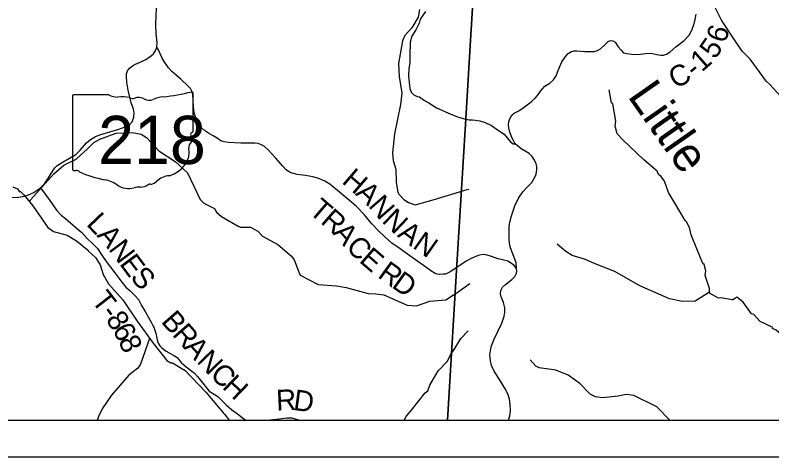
# Model space of a CAD drawing. Extents: x -1.8 to 75.7, y -2 to 25.
# Drawn here: x 46.582 to 48.65, y 15.612 to 16.82 of the extents above; entities that cross this region are included whole.
import ezdxf

# ---------------------------------------------------------------- set-up
doc = ezdxf.new("R2010")
doc.units = 0
for name, color, linetype in [('GM_X_County_Road', 7, 'Continuous'), ('GM_X_County_Road_Text', 7, 'Continuous'), ('GM_X_Minor_River', 7, 'Continuous'), ('GM_X_Minor_River_Text', 7, 'Continuous'), ('GM_X_State_Location', 7, 'Continuous'), ('GM_X_State_Route', 7, 'Continuous'), ('GM_X_State_Shield', 7, 'Continuous'), ('GM_X_Township', 7, 'Continuous'), ('GM_X_Township_Road', 7, 'Continuous'), ('GM_X_Township_Road_Text', 7, 'Continuous'), ('SH_Data', 7, 'Continuous')]:
    doc.layers.add(name, color=color, linetype=linetype)

msp = doc.modelspace()

# ---------------------------------------------------------------- linework, layer by layer
at = {"layer": 'GM_X_County_Road'}
for points in [[(47.7035, 16.83), (47.6954, 16.8181), (47.6889, 16.8088), (47.6859, 16.7983), (47.677, 16.7799), (47.6663, 16.7623), (47.6614, 16.7463), (47.6604, 16.7082), (47.6605, 16.6896), (47.6576, 16.6736), (47.6574, 16.6531), (47.6608, 16.6193), (47.6644, 16.6089), (47.6713, 16.6015), (47.6806, 16.5977), (47.6874, 16.5962), (47.7007, 16.5867), (47.7128, 16.5796), (47.7337, 16.5667), (47.7641, 16.5525), (47.788, 16.543), (47.8062, 16.5371), (47.8137, 16.5356), (47.8231, 16.5337), (47.8315, 16.5334)], [(47.9438, 16.4769), (47.9401, 16.4838), (47.9344, 16.5001), (47.9308, 16.5116), (47.93, 16.5197), (47.931, 16.5288), (47.9345, 16.5385), (47.9393, 16.5465), (47.946, 16.5517), (47.9582, 16.5584), (47.9708, 16.5667), (47.9923, 16.5826), (48.0028, 16.5927), (48.0091, 16.6), (48.0179, 16.6118), (48.0296, 16.6254), (48.0432, 16.6341), (48.053, 16.6428), (48.0597, 16.6522), (48.068, 16.6727), (48.0761, 16.6922), (48.0867, 16.7075), (48.0934, 16.7147), (48.1021, 16.72), (48.1092, 16.7224), (48.1171, 16.7226), (48.1392, 16.7208), (48.1554, 16.72), (48.1652, 16.7206), (48.1733, 16.723), (48.1819, 16.7279), (48.1935, 16.7383), (48.2027, 16.7473), (48.2088, 16.7502), (48.2157, 16.7496), (48.2214, 16.7457), (48.2301, 16.7329), (48.2378, 16.7242), (48.2447, 16.7171), (48.2531, 16.7149), (48.2669, 16.7129), (48.2827, 16.7126), (48.3048, 16.7149), (48.3204, 16.7155), (48.3356, 16.7122), (48.3462, 16.7104), (48.3543, 16.7106), (48.3624, 16.7133), (48.3718, 16.7198), (48.388, 16.7331), (48.4103, 16.7504), (48.4241, 16.7652), (48.4312, 16.7788), (48.4367, 16.7942), (48.4407, 16.8078), (48.443, 16.8224)], [(47.7998, 16.1373), (47.792, 16.1321), (47.7888, 16.1299), (47.7713, 16.1181), (47.7583, 16.112), (47.7514, 16.1112), (47.7429, 16.1104), (47.7352, 16.1118), (47.7295, 16.1138), (47.7177, 16.1203), (47.7048, 16.1303), (47.6609, 16.1615), (47.6339, 16.1806), (47.6118, 16.1968), (47.5923, 16.2141), (47.5751, 16.2305), (47.5572, 16.2488), (47.5355, 16.2751), (47.5142, 16.2975), (47.4968, 16.3125), (47.4681, 16.3354), (47.4422, 16.3575), (47.4284, 16.3663), (47.4123, 16.3732), (47.3959, 16.3776), (47.3756, 16.3815), (47.3527, 16.3837), (47.3387, 16.3874), (47.3318, 16.3902), (47.3229, 16.3967), (47.3135, 16.407), (47.2934, 16.4294), (47.274, 16.4517), (47.2638, 16.4606), (47.2555, 16.4655), (47.2464, 16.4685), (47.237, 16.4702), (47.223, 16.4695), (47.1991, 16.4698), (47.165, 16.4718), (47.1532, 16.4732), (47.1445, 16.4764), (47.1339, 16.4833), (47.123, 16.4902), (47.1102, 16.4971), (47.1, 16.5045), (47.0911, 16.512), (47.083, 16.5227), (47.0773, 16.5349), (47.0718, 16.5525), (47.0694, 16.5704), (47.0683, 16.5864), (47.0679, 16.6025), (47.0653, 16.6115), (47.0611, 16.6189), (47.0552, 16.6255), (47.0347, 16.6445), (47.0104, 16.6661), (47.0014, 16.676), (46.9894, 16.693), (46.9831, 16.7039), (46.9737, 16.7249), (46.9691, 16.7321)], [(47.8315, 16.5334), (47.84, 16.5331), (47.8522, 16.5305), (47.8666, 16.5265), (47.8837, 16.5181), (47.9034, 16.5043), (47.9188, 16.4946), (47.9353, 16.4739), (47.9431, 16.468), (47.9486, 16.4681)], [(47.9525, 16.1268), (47.9513, 16.1426), (47.9422, 16.1676), (47.9359, 16.1832), (47.9328, 16.1952), (47.932, 16.209), (47.9318, 16.226), (47.9322, 16.2417), (47.9337, 16.2536), (47.9385, 16.2715), (47.9479, 16.2987), (47.9576, 16.319), (47.9696, 16.3366), (47.9793, 16.348), (47.9937, 16.3626), (48.0014, 16.3746), (48.0059, 16.3853), (48.0079, 16.3965), (48.0073, 16.4058), (48.0057, 16.4129), (48.0014, 16.4237), (47.9947, 16.4334), (47.9866, 16.4411), (47.9759, 16.4478), (47.9653, 16.4547), (47.9486, 16.4681), (47.9438, 16.4769)], [(47.9305, 15.7121), (47.9343, 15.7245), (47.9354, 15.7379), (47.9347, 15.7564), (47.9329, 15.7696), (47.9281, 15.7844), (47.9213, 15.7983), (47.9101, 15.8163), (47.891, 15.846), (47.8839, 15.8622), (47.881, 15.8743), (47.8794, 15.8913), (47.8807, 15.9023), (47.8829, 15.9127), (47.8901, 15.9324), (47.9117, 15.9777), (47.9183, 15.9969), (47.9206, 16.0078), (47.9206, 16.0197), (47.917, 16.034), (47.9104, 16.0498), (47.9088, 16.058), (47.9092, 16.0666), (47.9136, 16.076), (47.9218, 16.0838), (47.9393, 16.0974), (47.948, 16.1054), (47.9521, 16.1145), (47.9532, 16.1211), (47.9525, 16.1268), (47.9458, 16.1353), (47.9389, 16.1406), (47.9286, 16.1467), (47.9174, 16.1499), (47.9018, 16.1538), (47.8785, 16.1621), (47.8683, 16.1646), (47.86, 16.165), (47.847, 16.1623), (47.8302, 16.1556), (47.8145, 16.1471), (47.7998, 16.1373)]]:
    msp.add_lwpolyline(points, dxfattribs=at)
at = {"layer": 'GM_X_Minor_River'}
for points in [[(48.675, 16.5965), (48.6436, 16.6309), (48.6355, 16.638), (48.5908, 16.6994), (48.5684, 16.721), (48.5438, 16.7582), (48.5128, 16.8063), (48.4718, 16.8889), (48.463, 16.8975), (48.437, 16.9504)], [(47.687, 16.835), (47.6834, 16.8146), (47.6658, 16.7852), (47.6471, 16.7645), (47.6402, 16.7499), (47.63, 16.6872), (47.6316, 16.6522), (47.6385, 16.6061), (47.6349, 16.5754), (47.6185, 16.4951), (47.6135, 16.4436), (47.6155, 16.4223), (47.6224, 16.3989), (47.6235, 16.3624), (47.628, 16.3357), (47.6305, 16.3307), (47.644, 16.3158), (47.657, 16.3074), (47.675, 16.3015), (47.7249, 16.3151), (47.8176, 16.3429), (47.8222, 16.3439)], [(48.5428, 16.0417), (48.51, 16.0467), (48.5044, 16.0463), (48.4798, 16.06), (48.4794, 16.0725), (48.4676, 16.1078), (48.4691, 16.1207), (48.4653, 16.1382), (48.4615, 16.1412), (48.4453, 16.1811), (48.4293, 16.2195), (48.4252, 16.2392), (48.4168, 16.2544), (48.4134, 16.2586), (48.3835, 16.3072), (48.3672, 16.3345), (48.3563, 16.366), (48.3475, 16.3789), (48.3404, 16.3842), (48.3362, 16.3933), (48.2995, 16.4252), (48.2439, 16.4782), (48.2272, 16.4953), (48.2219, 16.5162), (48.2238, 16.5299), (48.2154, 16.5774), (48.212, 16.5796), (48.2052, 16.6157)], [(46.6217, 16.3098), (46.6253, 16.3157), (46.6879, 16.3855), (46.7151, 16.4093), (46.7485, 16.4264), (46.78, 16.4547), (46.7971, 16.4712), (46.814, 16.4805), (46.858, 16.497), (46.9019, 16.4986), (46.9267, 16.4948), (46.9412, 16.4856), (46.9748, 16.4484), (47.0197, 16.4197), (47.0528, 16.3886), (47.0873, 16.3161), (47.0972, 16.3067), (47.1046, 16.3023), (47.1266, 16.2913), (47.1323, 16.2813), (47.1463, 16.2691), (47.1913, 16.2428)], [(46.5758, 16.3501), (46.5883, 16.3448), (46.5939, 16.3369), (46.5966, 16.3376), (46.606, 16.3285), (46.6306, 16.2982), (46.6533, 16.2652), (46.6719, 16.2394), (46.681, 16.2326), (46.687, 16.2284), (46.7241, 16.2182), (46.7498, 16.2027), (46.7793, 16.1788), (46.782, 16.1754), (46.8013, 16.1576), (46.8141, 16.1371), (46.8225, 16.1105), (46.8376, 16.0851), (46.8762, 16.0418), (46.9156, 15.9834), (46.9591, 15.9227), (46.9966, 15.876), (47.0075, 15.8692), (47.0125, 15.8696), (47.0469, 15.848), (47.1029, 15.7889), (47.1517, 15.7312), (47.1543, 15.7286), (47.1668, 15.7121)], [(47.1913, 16.2428), (47.1976, 16.2397), (47.2252, 16.2403), (47.2453, 16.2291), (47.2577, 16.2154), (47.3001, 16.1928), (47.3369, 16.1612), (47.3442, 16.1507), (47.3586, 16.1153), (47.3614, 16.1092), (47.4106, 16.0833), (47.4603, 16.0794), (47.4871, 16.0755), (47.547, 16.0588), (47.5682, 16.0578), (47.5892, 16.0552), (47.653, 16.0269), (47.6787, 16.0246), (47.715, 16.0375), (47.7589, 16.0414), (47.7801, 16.0552), (47.7863, 16.0591), (47.8242, 16.0864)], [(48.4794, 16.0623), (48.4403, 16.0378), (48.4055, 16.0367), (48.3702, 16.0443), (48.2889, 16.0799), (48.2205, 16.1189), (48.172, 16.1376), (48.1384, 16.1527), (48.1043, 16.1625), (48.0869, 16.1733), (48.0629, 16.1938)], [(48.8468, 15.7937), (48.8248, 15.8084), (48.7884, 15.8395), (48.7684, 15.8543), (48.7408, 15.888), (48.7377, 15.8884), (48.7059, 15.9294), (48.6799, 15.943), (48.6621, 15.9589), (48.6519, 15.9634), (48.6526, 15.9661), (48.6182, 15.9824), (48.6008, 16.0017), (48.5944, 16.0028), (48.5713, 16.0347), (48.5539, 16.0487), (48.5417, 16.0418), (48.5506, 16.0468)], [(47.6454, 15.7121), (47.6507, 15.7225), (47.6681, 15.7434), (47.7028, 15.7876), (47.71, 15.7922), (47.7149, 15.8081), (47.7383, 15.8473), (47.764, 15.8736), (47.7715, 15.8915), (47.7836, 15.9082), (47.7998, 15.9356), (47.8198, 15.957)], [(46.9496, 15.9359), (46.925, 15.8657), (46.9171, 15.8549), (46.8927, 15.8352), (46.845, 15.7805), (46.82, 15.7437), (46.8104, 15.7243), (46.8064, 15.7121)], [(48.3714, 15.7121), (48.3355, 15.7485), (48.273, 15.7797), (48.2515, 15.7823), (48.2298, 15.778), (48.187, 15.7733), (48.1682, 15.7762), (48.1533, 15.7839), (48.1254, 15.8125), (48.0933, 15.8356), (48.0593, 15.8488), (48.0141, 15.8552), (48.0048, 15.86), (47.9898, 15.8772)]]:
    msp.add_lwpolyline(points, dxfattribs=at)
at = {"layer": 'GM_X_State_Route'}
msp.add_lwpolyline([(46.5737, 16.3208), (46.5925, 16.3217), (46.6067, 16.3247), (46.619, 16.3285), (46.6336, 16.335), (46.6513, 16.3473), (46.6625, 16.3588), (46.6732, 16.3746), (46.6898, 16.4015), (46.6966, 16.4087), (46.713, 16.4185), (46.7484, 16.4391), (46.7599, 16.4506), (46.7774, 16.4703), (46.7881, 16.4799), (46.8015, 16.4882), (46.8161, 16.4935), (46.8657, 16.5077), (46.8832, 16.514), (46.8946, 16.5201), (46.9018, 16.5284), (46.9068, 16.5405), (46.9077, 16.5514), (46.9055, 16.5625), (46.8996, 16.58), (46.8906, 16.6148), (46.8869, 16.6366), (46.8861, 16.6517), (46.8865, 16.6596), (46.8889, 16.6677), (46.8946, 16.6751), (46.9024, 16.6816), (46.9106, 16.6856), (46.9239, 16.691), (46.937, 16.6978), (46.9505, 16.7059), (46.9606, 16.7144), (46.9656, 16.7225), (46.9691, 16.7321), (46.9698, 16.7446), (46.9676, 16.7684), (46.9667, 16.7953), (46.968, 16.839)], dxfattribs=at)
at = {"layer": 'GM_X_State_Shield'}
for p, q in [((47.0683, 16.5024), (47.0683, 16.6071)), ((46.7387, 16.5987), (46.7387, 16.3986)), ((46.8384, 16.6021), (46.7419, 16.6021)), ((47.0682, 16.5024), (47.0683, 16.5024))]:
    msp.add_line(p, q, dxfattribs=at)
for centre, major_axis, start_param, end_param in [((46.9509, 16.875), (0.3495, 0), 4.814394, 5.042369), ((47.0646, 16.6075), (0.00367, 0), 6.141152, 7.989035), ((46.7424, 16.5991), (0.00382, 0), 1.712693, 3.28349), ((46.8614, 16.6254), (0.037, 0), 4.042523, 4.731795), ((46.8737, 16.4898), (0.133, 0), 1.404758, 1.657858), ((46.9039, 16.6001), (0.0107, 0), 3.836095, 5.185415), ((46.9196, 16.577), (0.0222, 0), 0.950623, 2.079405), ((46.9482, 16.6087), (0.0267, 0), 4.081561, 5.145723), ((46.9954, 16.541), (0.0703, 0), 1.699011, 2.107814), ((47.0643, 16.502), (0.00393, 0), 5.05454, 6.418171), ((47.0674, 16.4947), (0.00568, 0), 1.883978, 3.671073), ((47.0313, 16.4815), (0.0341, 0), 5.934695, 6.695948), ((47.0814, 16.4586), (0.0248, 0), 2.387724, 3.262537), ((46.9704, 16.4453), (0.0874, 0), 5.101752, 6.440018), ((46.7425, 16.3981), (0.00385, 0), 3.00124, 4.508301), ((46.7431, 16.4186), (0.0294, 0), 4.665946, 4.897461), ((46.7491, 16.387), (0.0106, 0), 0.519207, 1.627899), ((46.8829, 16.5668), (0.2524, 0), 4.195997, 4.488961), ((47.0073, 16.3424), (0.0479, 0), 1.647645, 2.488434), ((46.8077, 16.3087), (0.079, 0), 0.823519, 1.323587), ((46.9498, 16.3517), (0.00752, 0), 1.147584, 2.315152), ((46.9466, 16.3792), (0.0282, 0), 4.937069, 5.64225), ((46.8931, 16.386), (0.0501, 0), 4.026481, 4.996735), ((46.922, 16.3168), (0.0412, 0), 1.495662, 1.94098), ((46.9257, 16.371), (0.0267, 0), 4.691044, 5.507374)]:
    msp.add_ellipse(centre, major_axis=major_axis, ratio=0.8, start_param=start_param, end_param=end_param, dxfattribs=at)
at = {"layer": 'GM_X_Township'}
for points in [[(43.8002, 18.978), (43.8002, 15.7121), (47.7632, 15.7121)], [(47.7632, 15.7121), (47.7893, 16.1371), (47.8138, 16.5363), (47.826, 16.7363), (47.8708, 17.4759), (47.8899, 17.791), (47.9266, 18.366), (47.9522, 18.7663), (47.1815, 18.806), (46.9192, 18.8195), (46.3714, 18.8466), (46.1197, 18.859), (45.3865, 18.8952), (44.8356, 18.9224), (43.8002, 18.978)], [(50.6002, 18.6397), (50.591, 18.6401), (50.1896, 18.6602), (49.0051, 18.7193), (48.8964, 18.7242), (47.9522, 18.7663), (47.9266, 18.366), (47.8899, 17.791), (47.8708, 17.4759), (47.826, 16.7363), (47.8138, 16.5363), (47.7893, 16.1371), (47.7632, 15.7121)], [(47.7632, 15.7121), (50.6002, 15.7121), (50.6002, 18.6397)]]:
    msp.add_lwpolyline(points, dxfattribs=at)
at = {"layer": 'GM_X_Township_Road'}
for points in [[(46.6513, 16.3473), (46.677, 16.3128), (46.695, 16.287), (46.7082, 16.2729), (46.7194, 16.2638), (46.7476, 16.2396), (46.764, 16.2257), (46.7786, 16.2095), (46.7943, 16.195), (46.8073, 16.1815), (46.8187, 16.1635), (46.8308, 16.1462), (46.8543, 16.115), (46.8734, 16.0894), (46.8846, 16.076), (46.8951, 16.0666), (46.9099, 16.0527), (46.9193, 16.042), (46.9277, 16.0258), (46.9373, 16.0094), (46.9535, 15.98), (46.9592, 15.9696)], [(46.9592, 15.9696), (46.9607, 15.9668), (46.9669, 15.9506), (46.9699, 15.9319), (46.9726, 15.923), (46.9772, 15.916), (46.9838, 15.9089), (46.9952, 15.9011), (47.018, 15.8879), (47.0246, 15.8836), (47.0357, 15.8701), (47.0499, 15.8578), (47.072, 15.841), (47.0804, 15.8316), (47.095, 15.8136), (47.1046, 15.801)], [(47.1046, 15.801), (47.1057, 15.7995), (47.1123, 15.7917), (47.1262, 15.7833), (47.1363, 15.7771), (47.1604, 15.7525), (47.1734, 15.7414), (47.1898, 15.7293), (47.2072, 15.7158), (47.2136, 15.7121)], [(47.2702, 15.7121), (47.2963, 15.7154), (47.3245, 15.7188), (47.338, 15.7186), (47.3569, 15.7133), (47.3615, 15.7121)]]:
    msp.add_lwpolyline(points, dxfattribs=at)
at = {"layer": 'SH_Data'}
for p, q in [((43.8002, 15.7121), (50.6002, 15.7121)), ((43.8002, 15.7121), (50.6002, 15.7121)), ((43.7002, 15.6121), (50.7002, 15.6121))]:
    msp.add_line(p, q, dxfattribs=at)

# ---------------------------------------------------------------- texts
at = {"layer": 'GM_X_County_Road_Text'}
for s, rotation, p in [('6', 71.0324, (48.5222, 16.7408)), ('5', 55.3666, (48.4947, 16.6969)), ('1', 41.5097, (48.4585, 16.6625)), ('C', 26.6261, (48.3858, 16.6175)), ('-', 40.4737, (48.44, 16.6466)), ('H', 319.4556, (47.4724, 16.3625)), ('A', 316.9297, (47.5099, 16.3304)), ('T', 319.5063, (47.3822, 16.2803)), ('N', 310.932, (47.5453, 16.2974)), ('R', 318.886, (47.4144, 16.2528)), ('N', 316.5339, (47.5822, 16.2552)), ('A', 311.2869, (47.4481, 16.2235)), ('A', 323.4664, (47.6243, 16.216)), ('N', 324.9857, (47.6658, 16.1853)), ('C', 314.4447, (47.4834, 16.1835)), ('E', 319.17, (47.5199, 16.1466)), ('R', 324.1743, (47.5702, 16.1048)), ('D', 324.6199, (47.6084, 16.0773))]:
    msp.add_text(s, height=0.0568, rotation=rotation, dxfattribs=at).set_placement(p)
at = {"layer": 'GM_X_Minor_River_Text'}
msp.add_text('Little', height=0.09469, rotation=304.9993, dxfattribs=at).set_placement((48.254, 16.5986))
at = {"layer": 'GM_X_State_Location'}
for s in ['s', 'r']:
    msp.add_text(s, height=0.000189, dxfattribs=at).set_placement((46.8998, 16.4853))
msp.add_text('218', height=0.000189, rotation=0, dxfattribs=at).set_placement((46.8329, 16.4715))
at = {"layer": 'GM_X_State_Shield'}
msp.add_text('218', height=0.13184, dxfattribs=at).set_placement((46.809, 16.4127))
at = {"layer": 'GM_X_Township_Road_Text'}
for s, rotation, p in [('L', 313.7196, (46.7746, 16.247)), ('A', 310.7937, (46.8035, 16.2168)), ('N', 306.8054, (46.8355, 16.1798)), ('E', 306.7165, (46.8654, 16.1398)), ('S', 312.0447, (46.8945, 16.1013)), ('T', 308.0554, (46.7887, 16.0386)), ('-', 306.8199, (46.8147, 16.0054)), ('8', 303.4072, (46.8282, 15.9875)), ('B', 311.3477, (46.9789, 15.981)), ('6', 298.8464, (46.8468, 15.9593)), ('R', 311.3464, (47.0097, 15.946)), ('8', 293.6243, (46.8631, 15.9298)), ('A', 311.6869, (47.0408, 15.9107)), ('N', 314.0513, (47.0758, 15.8715)), ('C', 315.9732, (47.112, 15.8341)), ('H', 316.1221, (47.1457, 15.8015)), ('R', 2.5241, (47.2965, 15.7384)), ('D', 352.274, (47.3405, 15.7406))]:
    msp.add_text(s, height=0.0568, rotation=rotation, dxfattribs=at).set_placement(p)

doc.saveas('drawing.dxf')
